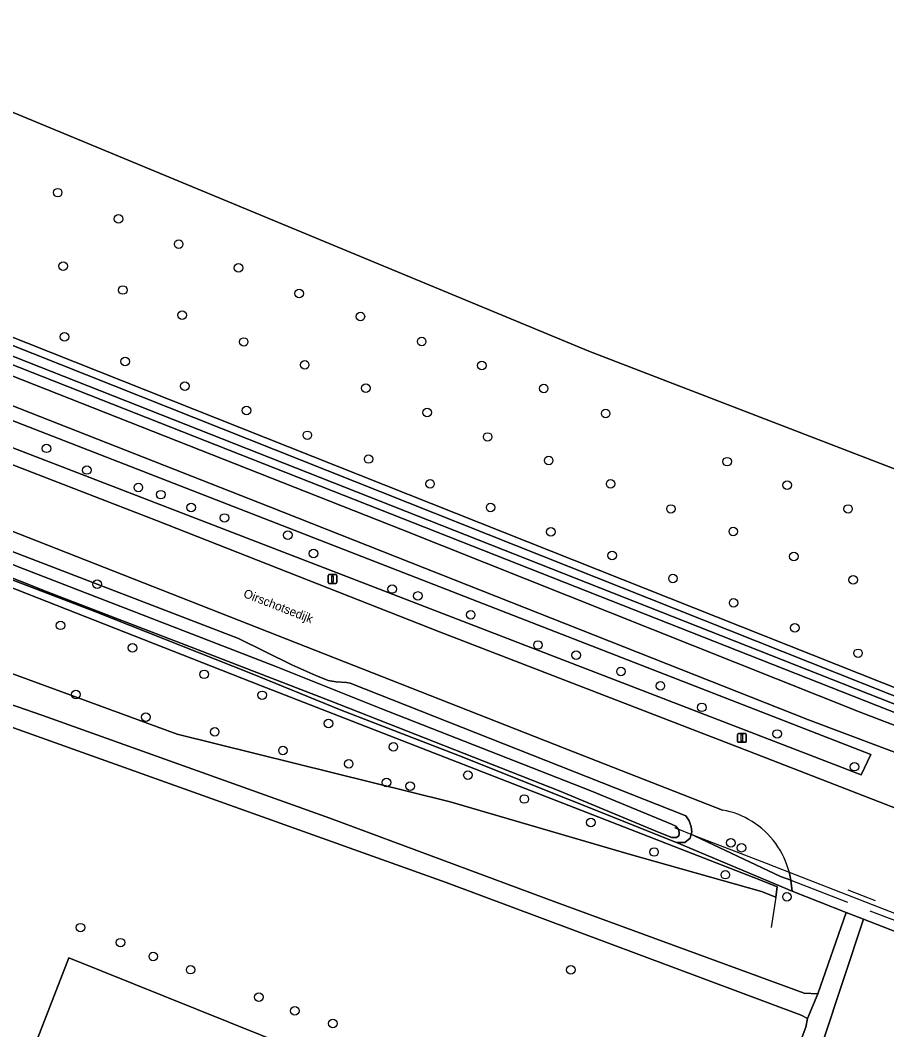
# Model space of a CAD drawing. Extents: x 155209 to 156748, y 385356 to 388487.
# Drawn here: x 155554.2 to 155653.4, y 386739.4 to 386855.1 of the extents above; entities that cross this region are included whole.
import ezdxf

# ---------------------------------------------------------------- set-up
doc = ezdxf.new("R2010")
doc.units = 0
for name, color, linetype in [('IMGEO_Berm_groen', 7, 'Continuous'), ('IMGEO_Boom', 7, 'Continuous'), ('IMGEO_Bouwland', 7, 'Continuous'), ('IMGEO_Duiker', 7, 'Continuous'), ('IMGEO_Fietspad_gesloten', 7, 'Continuous'), ('IMGEO_Gemengd_bos', 7, 'Continuous'), ('IMGEO_Groenvoorziening', 7, 'Continuous'), ('IMGEO_Hek', 7, 'Continuous'), ('IMGEO_Lichtmast', 7, 'Continuous'), ('IMGEO_Oever', 7, 'Continuous'), ('IMGEO_Openbare_ruimte_label', 7, 'Continuous'), ('IMGEO_Rijbaan_lokaal_gesloten', 7, 'Continuous'), ('IMGEO_Rijbaan_lokaal_halfverhard', 7, 'Continuous'), ('IMGEO_Waterloop', 7, 'Continuous')]:
    doc.layers.add(name, color=color, linetype=linetype)

msp = doc.modelspace()

# ---------------------------------------------------------------- linework, layer by layer
at = {"layer": 'IMGEO_Berm_groen'}
for points in [[(155476.96, 386846.12), (155486.55, 386842.14), (155500, 386836.47), (155529.41, 386824.07), (155542.24, 386818.67), (155597.75, 386796.8), (155650.37, 386775.84), (155664.94, 386770.25), (155717.68, 386750), (155777.32, 386727.1), (155776.91, 386729.81), (155728.33, 386750), (155696.05, 386763.44)], [(155660.25, 386773.45), (155544.85, 386818.92), (155529.93, 386825.41), (155500, 386838.42), (155487.29, 386843.95), (155482.51, 386846.03)], [(155475.22, 386841.64), (155484.65, 386837.49), (155500, 386830.78), (155511.58, 386825.73), (155520.65, 386822.29), (155527.61, 386819.45), (155541.14, 386813.94), (155651.62, 386770.97), (155650.5, 386768.64)], [(155650.5, 386768.64), (155526.43, 386816.44), (155523.28, 386817.66), (155500, 386827.48), (155499.42, 386827.72), (155473.59, 386839.43)], [(155634.6, 386764.62), (155617.56, 386771.28), (155523.26, 386808.3), (155500, 386817.43), (155496.81, 386818.68), (155478.14, 386825.82)], [(155552.56, 386794.49), (155579.17, 386784.25), (155585.27, 386781.26), (155588.04, 386780.02), (155589.43, 386779.44), (155590.36, 386779.31), (155591.53, 386779.21), (155591.96, 386779.14), (155630.4, 386763.97), (155630.81, 386763.38), (155631.03, 386762.7), (155631.09, 386762.12), (155631.02, 386761.84), (155631.41, 386761.68), (155641.27, 386757.02), (155642.45, 386756.57), (155642.3, 386757.34), (155642.28, 386757.45)]]:
    msp.add_lwpolyline(points, dxfattribs=at)
msp.add_lwpolyline([(155657.25, 386770.12), (155644.46, 386774.96), (155582.64, 386799.4), (155542.08, 386815.32), (155528.28, 386821.17), (155500, 386833.17), (155494.87, 386835.35), (155485.35, 386839.2), (155476.04, 386842.96), (155472.84, 386844.21), (155470.47, 386841.01), (155471.87, 386835.61), (155498.72, 386825.29), (155500, 386824.8), (155508.89, 386821.38), (155525.8, 386814.81), (155543.69, 386807.85), (155569.76, 386797.77), (155602.21, 386785.04), (155637.7, 386771.32), (155656.5, 386764.02), (155656.85, 386765.03), (155658.22, 386768.43)], close=True, dxfattribs=at)
for centre, radius, start, end in [((155632.9, 386755.1), 9.67, 58.1118, 79.8493), ((155632.9, 386755.11), 9.66, 14.0116, 58.0942)]:
    msp.add_arc(centre, radius, start, end, dxfattribs=at)
at = {"layer": 'IMGEO_Boom'}
for centre in [(155558.45, 386835.33), (155565.41, 386832.34), (155572.31, 386829.43), (155559.07, 386826.92), (155579.17, 386826.71), (155565.91, 386824.18), (155586.12, 386823.77), (155572.71, 386821.29), (155593.13, 386821.14), (155559.22, 386818.81), (155579.76, 386818.23), (155600.15, 386818.28), (155566.19, 386815.98), (155586.75, 386815.6), (155607.04, 386815.53), (155573.01, 386813.16), (155593.75, 386812.94), (155614.13, 386812.89), (155580.07, 386810.39), (155600.79, 386810.14), (155621.23, 386810.04), (155587.05, 386807.54), (155607.71, 386807.35), (155557.17, 386806.04), (155594.07, 386804.82), (155614.7, 386804.66), (155635.14, 386804.52), (155561.78, 386803.56), (155601.11, 386801.99), (155621.8, 386801.98), (155642.03, 386801.83), (155567.69, 386801.57), (155570.26, 386800.74), (155573.73, 386799.26), (155608.05, 386799.28), (155628.71, 386799.1), (155649, 386799.1), (155577.55, 386798.07), (155584.81, 386796.11), (155614.95, 386796.48), (155635.85, 386796.51), (155587.75, 386794), (155621.97, 386793.77), (155642.78, 386793.65), (155562.97, 386790.48), (155628.94, 386791.13), (155649.58, 386790.98), (155596.77, 386789.93), (155599.71, 386789.14), (155635.89, 386788.34), (155605.77, 386786.98), (155558.76, 386785.77), (155642.9, 386785.48), (155613.47, 386783.52), (155567.02, 386783.19), (155617.84, 386782.36), (155650.14, 386782.57), (155575.22, 386780.16), (155622.98, 386780.48), (155627.5, 386778.85), (155560.53, 386777.84), (155581.87, 386777.76), (155632.24, 386776.38), (155568.55, 386775.26), (155589.47, 386774.52), (155576.44, 386773.57), (155640.87, 386773.33), (155596.91, 386771.85), (155584.26, 386771.44), (155591.79, 386769.9), (155649.73, 386769.58), (155605.45, 386768.62), (155596.13, 386767.78), (155598.84, 386767.34), (155611.91, 386765.88), (155619.52, 386763.18), (155635.58, 386760.85), (155636.79, 386760.3), (155626.77, 386759.81), (155634.94, 386757.21), (155642, 386754.68), (155561.06, 386751.15), (155565.64, 386749.43), (155569.4, 386747.84), (155573.68, 386746.33), (155617.25, 386746.31), (155581.49, 386743.19), (155585.61, 386741.61), (155589.98, 386740.17)]:
    msp.add_circle(centre, 0.489, dxfattribs=at)
at = {"layer": 'IMGEO_Bouwland'}
msp.add_lwpolyline([(155501.63, 386865.96), (155619.3, 386817.16), (155711.43, 386781.69), (155736.11, 386805.05), (155771.1, 386838.59), (155794.24, 386860.52)], dxfattribs=at)
at = {"layer": 'IMGEO_Duiker'}
msp.add_lwpolyline([(155666.33, 386748.06), (155664.02, 386748.99), (155661.42, 386750), (155656.8, 386751.8), (155642.28, 386757.45), (155639.65, 386758.48), (155631.41, 386761.68), (155629.14, 386762.58)], dxfattribs=at)
at = {"layer": 'IMGEO_Fietspad_gesloten'}
msp.add_lwpolyline([(155413.36, 386866.62), (155414.23, 386866.33), (155418.72, 386864.51), (155466.77, 386846.51), (155472.84, 386844.21), (155476.04, 386842.96), (155485.35, 386839.2), (155494.87, 386835.35), (155500, 386833.17), (155528.28, 386821.17), (155542.08, 386815.32), (155582.64, 386799.4), (155644.46, 386774.96), (155657.25, 386770.12), (155663.89, 386767.51), (155664.94, 386770.25), (155650.37, 386775.84), (155597.75, 386796.8), (155542.24, 386818.67), (155529.41, 386824.07)], dxfattribs=at)
at = {"layer": 'IMGEO_Gemengd_bos'}
for points in [[(155619.3, 386817.16), (155501.63, 386865.96), (155500, 386864.42), (155495.58, 386860.26), (155487.22, 386852.8), (155483.84, 386849.41)], [(155484.42, 386847.58), (155500, 386841.03), (155546.79, 386821.35), (155661.24, 386775.91), (155666.7, 386773.84), (155690.08, 386764.42), (155695.12, 386766.26), (155711.43, 386781.69), (155619.3, 386817.16)], [(155634.14, 386713.25), (155644.18, 386739.73), (155644.34, 386740.74), (155643.64, 386741.11), (155602.96, 386756.31), (155548.13, 386775.92), (155545.77, 386776.43)]]:
    msp.add_lwpolyline(points, dxfattribs=at)
msp.add_lwpolyline([(155554.38, 386733.89), (155559.71, 386747.69), (155614.71, 386725.57), (155610.76, 386716.71), (155609.34, 386713.39), (155608.88, 386711.8), (155588.92, 386719.73), (155589.49, 386721.25), (155583.96, 386723.33), (155583.26, 386721.79), (155571.06, 386726.49), (155571.68, 386727.98), (155567.07, 386729.53), (155566.62, 386728.16), (155557.06, 386731.77), (155557.42, 386732.74)], close=True, dxfattribs=at)
at = {"layer": 'IMGEO_Groenvoorziening'}
for points in [[(155456.91, 386813.08), (155476.48, 386805.75), (155488.01, 386801.68), (155505.08, 386795.32), (155519.31, 386789.64), (155532.09, 386790.73), (155540.07, 386789.5), (155551.59, 386780.84), (155572.12, 386773.29), (155603.41, 386765.55), (155623.92, 386759.56), (155639.1, 386755.3), (155640.71, 386754.64), (155640.89, 386755.83), (155638.9, 386756.61), (155581.69, 386778.9), (155551.64, 386790.69), (155520.82, 386802.04), (155484.11, 386815.5), (155477.84, 386817.46), (155463.65, 386822.31)], [(155511.9, 386806.37), (155500, 386810.91), (155489.2, 386815.03), (155475.66, 386819.02), (155464.51, 386822.78), (155463.65, 386822.31), (155477.84, 386817.46), (155484.11, 386815.5), (155520.82, 386802.04), (155551.64, 386790.69), (155581.69, 386778.9), (155638.9, 386756.61), (155640.89, 386755.83), (155640.71, 386754.64), (155639.1, 386755.3), (155623.92, 386759.56), (155603.41, 386765.55), (155572.12, 386773.29), (155551.59, 386780.84), (155540.07, 386789.5), (155532.09, 386790.73), (155519.31, 386789.64), (155522.15, 386788.5), (155524.3, 386788.11)], [(155548.01, 386778.45), (155556.62, 386775.48), (155589.64, 386763.7), (155615.52, 386754.06), (155643.96, 386743.63), (155645.55, 386743.55), (155648.8, 386752.89), (155642.58, 386755.34), (155629.33, 386760.9), (155604.5, 386770.82), (155590.94, 386776.05), (155580.53, 386780.3), (155562.69, 386787.37), (155529.27, 386800.13), (155519.03, 386804.42), (155511.9, 386806.37)], [(155687.33, 386713.23), (155695.66, 386734.59), (155661.19, 386747.92), (155654.58, 386750.61), (155650.78, 386752.11), (155646.13, 386738.19), (155636.4, 386712.24), (155627.03, 386686.65), (155606.99, 386633), (155605.46, 386628.53), (155594.88, 386600.99), (155587.3, 386580.96)]]:
    msp.add_lwpolyline(points, dxfattribs=at)
for points in [[(155631.02, 386761.84), (155630.91, 386761.41), (155630.3, 386760.91), (155629.33, 386760.9), (155642.58, 386755.34), (155642.55, 386755.63), (155642.46, 386756.49), (155642.45, 386756.57), (155641.27, 386757.02), (155631.41, 386761.68)], [(155559.71, 386747.69), (155554.38, 386733.89), (155557.42, 386732.74), (155557.55, 386733.04), (155567.07, 386729.53), (155571.68, 386727.98), (155583.96, 386723.33), (155589.49, 386721.25), (155609.34, 386713.39), (155610.76, 386716.71), (155614.71, 386725.57)]]:
    msp.add_lwpolyline(points, close=True, dxfattribs=at)
at = {"layer": 'IMGEO_Hek'}
for points in [[(155581.69, 386778.9), (155551.64, 386790.69), (155520.82, 386802.04)], [(155581.69, 386778.9), (155638.9, 386756.61)], [(155638.9, 386756.61), (155640.89, 386755.83)], [(155641.27, 386757.02), (155642.45, 386756.57)], [(155642.45, 386756.57), (155648.93, 386754.08)], [(155640.89, 386755.83), (155640.71, 386754.64)], [(155648.97, 386755.46), (155652.09, 386754.26)], [(155640.71, 386754.64), (155640.18, 386751.15)], [(155651.51, 386753.09), (155655.94, 386751.39)]]:
    msp.add_lwpolyline(points, dxfattribs=at)
at = {"layer": 'IMGEO_Lichtmast'}
for p, q in [((155589.43, 386790.68), (155589.43, 386791.48)), ((155589.43, 386791.48), (155589.43, 386790.68)), ((155589.53, 386791.58), (155590.32, 386791.58)), ((155590.32, 386791.58), (155589.53, 386791.58)), ((155590.42, 386791.48), (155590.42, 386790.68)), ((155590.42, 386790.68), (155590.42, 386791.48)), ((155590.32, 386790.58), (155589.53, 386790.58)), ((155589.53, 386790.58), (155590.32, 386790.58)), ((155636.35, 386772.48), (155636.35, 386773.28)), ((155636.35, 386773.28), (155636.35, 386772.48)), ((155636.45, 386773.38), (155637.24, 386773.38)), ((155637.24, 386773.38), (155636.45, 386773.38)), ((155637.24, 386772.38), (155636.45, 386772.38)), ((155636.45, 386772.38), (155637.24, 386772.38)), ((155637.34, 386773.28), (155637.34, 386772.48)), ((155637.34, 386772.48), (155637.34, 386773.28))]:
    msp.add_line(p, q, dxfattribs=at)
for points in [[(155589.85, 386791.46), (155590, 386791.46), (155590, 386790.71), (155589.85, 386790.71), (155589.85, 386791.46)], [(155636.77, 386773.26), (155636.92, 386773.26), (155636.92, 386772.51), (155636.77, 386772.51), (155636.77, 386773.26)]]:
    msp.add_lwpolyline(points, dxfattribs=at)
for centre, start, end in [((155589.53, 386791.48), 90, 180), ((155589.53, 386791.48), 90, 180), ((155590.32, 386791.48), 0, 90), ((155590.32, 386791.48), 360, 90), ((155589.53, 386790.68), 180, 270), ((155589.53, 386790.68), 180, 270), ((155590.32, 386790.68), 270, 0), ((155590.32, 386790.68), 270, 0), ((155636.45, 386773.28), 90, 180), ((155636.45, 386773.28), 90, 180), ((155636.45, 386772.48), 180, 270), ((155636.45, 386772.48), 180, 270), ((155637.24, 386773.28), 0, 90), ((155637.24, 386773.28), 360, 90), ((155637.24, 386772.48), 270, 0), ((155637.24, 386772.48), 270, 0)]:
    msp.add_arc(centre, 0.1, start, end, dxfattribs=at)
at = {"layer": 'IMGEO_Oever'}
for points in [[(155660.55, 386774.4), (155660.33, 386774.45), (155659.68, 386774.64), (155545.2, 386819.76), (155530.29, 386826.24), (155500.36, 386839.25), (155487.65, 386844.78), (155482.06, 386847.19)], [(155484.06, 386846.75), (155499.65, 386840.19), (155546.44, 386820.52), (155659.93, 386775.45), (155660.76, 386775.11)], [(155482.51, 386846.03), (155487.29, 386843.95), (155500, 386838.42), (155529.93, 386825.41), (155544.85, 386818.92), (155660.25, 386773.45)], [(155661.42, 386775.37), (155661.34, 386775.64), (155661.24, 386775.91), (155546.79, 386821.35)], [(155529.27, 386800.13), (155562.69, 386787.37), (155580.53, 386780.3), (155590.94, 386776.05), (155604.5, 386770.82), (155629.33, 386760.9), (155630.3, 386760.91), (155630.91, 386761.41), (155631.02, 386761.84), (155631.09, 386762.12), (155631.03, 386762.7), (155630.81, 386763.38), (155630.4, 386763.97), (155591.96, 386779.14), (155591.53, 386779.21), (155590.36, 386779.31), (155589.43, 386779.44), (155588.04, 386780.02), (155585.27, 386781.26), (155579.17, 386784.25), (155552.56, 386794.49)], [(155533.91, 386800.4), (155554.54, 386792.23), (155583.24, 386781.13), (155595.49, 386776.25), (155619.52, 386766.83), (155628.76, 386763), (155629.26, 386762.78), (155629.63, 386762.34), (155629.66, 386761.94), (155629.61, 386761.66), (155629.34, 386761.48), (155628.82, 386761.48), (155627.35, 386762.06), (155615.9, 386766.82), (155589.65, 386777.14), (155574.54, 386782.97), (155557.23, 386789.62), (155547.51, 386793.47)]]:
    msp.add_lwpolyline(points, dxfattribs=at)
at = {"layer": 'IMGEO_Rijbaan_lokaal_gesloten'}
for points in [[(155388.05, 386860.73), (155422.59, 386847.21), (155447.01, 386837.97), (155453.66, 386835.34), (155457.34, 386833.96), (155460.36, 386832.83), (155464.21, 386831.23), (155478.14, 386825.82), (155496.81, 386818.68), (155500, 386817.43), (155523.26, 386808.3), (155617.56, 386771.28), (155634.6, 386764.62)], [(155666.03, 386752.22), (155666.17, 386752.49), (155668.79, 386759.03), (155660.26, 386762.49), (155656.5, 386764.02), (155637.7, 386771.32), (155602.21, 386785.04), (155569.76, 386797.77), (155543.69, 386807.85), (155525.8, 386814.81)], [(155642.28, 386757.45), (155642.3, 386757.34), (155642.45, 386756.57), (155642.46, 386756.49), (155642.55, 386755.63), (155642.58, 386755.34), (155648.8, 386752.89), (155650.78, 386752.11), (155654.58, 386750.61), (155654.7, 386750.68), (155655.73, 386751.29), (155655.94, 386751.39), (155656.8, 386751.8)]]:
    msp.add_lwpolyline(points, dxfattribs=at)
for centre, radius, start, end in [((155632.9, 386755.1), 9.67, 58.1118, 79.8493), ((155632.9, 386755.11), 9.66, 14.0116, 58.0942)]:
    msp.add_arc(centre, radius, start, end, dxfattribs=at)
at = {"layer": 'IMGEO_Rijbaan_lokaal_halfverhard'}
for points in [[(155545.77, 386776.43), (155548.13, 386775.92), (155602.96, 386756.31), (155643.64, 386741.11), (155644.34, 386740.74), (155645.55, 386743.55), (155643.96, 386743.63), (155615.52, 386754.06), (155589.64, 386763.7), (155556.62, 386775.48), (155548.01, 386778.45)], [(155587.3, 386580.96), (155594.88, 386600.99), (155605.46, 386628.53), (155606.99, 386633), (155627.03, 386686.65), (155636.4, 386712.24), (155646.13, 386738.19), (155650.78, 386752.11), (155648.8, 386752.89), (155645.55, 386743.55), (155644.34, 386740.74), (155644.18, 386739.73), (155634.14, 386713.25), (155624.86, 386687.72), (155604.83, 386634.04), (155593.26, 386603.28), (155584.86, 386581.8)]]:
    msp.add_lwpolyline(points, dxfattribs=at)
at = {"layer": 'IMGEO_Waterloop'}
for points in [[(155482.06, 386847.19), (155487.65, 386844.78), (155500.36, 386839.25), (155530.29, 386826.24), (155545.2, 386819.76), (155659.68, 386774.64), (155660.33, 386774.45), (155660.55, 386774.4)], [(155660.76, 386775.11), (155659.93, 386775.45), (155546.44, 386820.52), (155499.65, 386840.19), (155484.06, 386846.75)], [(155473.59, 386839.43), (155499.42, 386827.72), (155500, 386827.48), (155523.28, 386817.66), (155526.43, 386816.44), (155650.5, 386768.64), (155651.62, 386770.97), (155541.14, 386813.94), (155527.61, 386819.45), (155520.65, 386822.29), (155511.58, 386825.73), (155500, 386830.78), (155484.65, 386837.49), (155475.22, 386841.64)], [(155547.51, 386793.47), (155557.23, 386789.62), (155574.54, 386782.97), (155589.65, 386777.14), (155615.9, 386766.82), (155627.35, 386762.06), (155628.82, 386761.48), (155629.34, 386761.48), (155629.61, 386761.66), (155629.66, 386761.94), (155629.63, 386762.34), (155629.26, 386762.78), (155628.76, 386763), (155619.52, 386766.83), (155595.49, 386776.25), (155583.24, 386781.13), (155554.54, 386792.23), (155533.91, 386800.4)]]:
    msp.add_lwpolyline(points, dxfattribs=at)

# ---------------------------------------------------------------- texts
at = {"layer": 'IMGEO_Openbare_ruimte_label'}
msp.add_text('Oirschotsedijk', height=1, rotation=338.7198, dxfattribs=at).set_placement((155579.64, 386789.04))

doc.saveas('drawing.dxf')
